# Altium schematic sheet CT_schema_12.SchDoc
size 278 x 170 mm
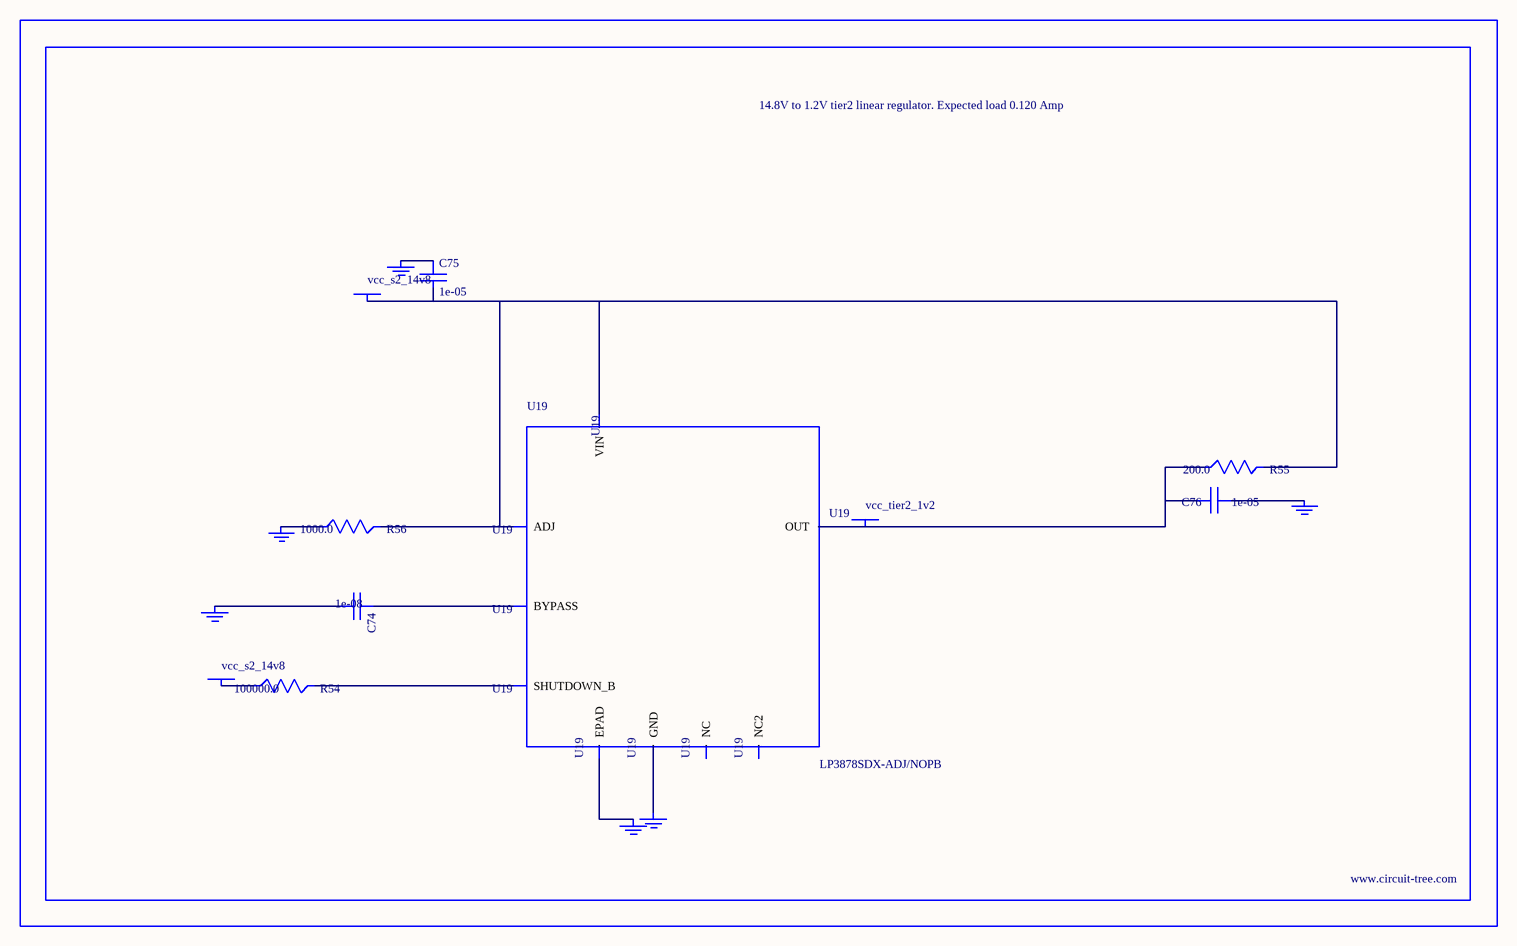
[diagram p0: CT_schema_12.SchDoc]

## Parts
BORDER11  (no value)
C74  1e-08  [C0402]
C75  1e-05  [C1210]
C76  1e-05  [C0805]
GND_INSTANCE_11_0  (no value)
GND_INSTANCE_11_1  (no value)
GND_INSTANCE_11_2  (no value)
GND_INSTANCE_11_3  (no value)
GND_INSTANCE_11_4  (no value)
GND_INSTANCE_11_5  (no value)
POWER_INSTANCE_11_0  vcc_s2_14v8
POWER_INSTANCE_11_1  vcc_s2_14v8
POWER_INSTANCE_11_2  vcc_tier2_1v2
R54  100000.0  [R0603]
R55  200.0  [R0603]
R56  1000.0  [R0603]
U19  LP3878SDX-ADJ/NOPB  [WSON-8]

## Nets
NetC74_1: C74.1 U19.1(BYPASS)
NetC74_2: C74.2 GND_INSTANCE_11_0.0(GND)
NetC75_1: C75.1 GND_INSTANCE_11_1.0(GND)
NetC75_2: C75.2 POWER_INSTANCE_11_0.0(PWR) R55.2 R56.2 U19.4(VIN) U19.6(ADJ)
NetC76_1: C76.1 GND_INSTANCE_11_2.0(GND)
NetC76_2: C76.2 POWER_INSTANCE_11_2.0(PWR) R55.1 U19.5(OUT)
NetGND_INSTANCE_11_3_0: GND_INSTANCE_11_3.0(GND) R56.1
NetGND_INSTANCE_11_4_0: GND_INSTANCE_11_4.0(GND) U19.PAD(EPAD)
NetGND_INSTANCE_11_5_0: GND_INSTANCE_11_5.0(GND) U19.3(GND)
NetPOWER_INSTANCE_11_1_0: POWER_INSTANCE_11_1.0(PWR) R54.1
NetR54_2: R54.2 U19.8(SHUTDOWN_B)

Not connected (* = marked no-connect by the designer): U19 2(NC) 7(NC2)

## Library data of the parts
BORDER11 = BORDER_PAGE11
C74 = C0402C103K3RAC
C75 = C1210C106K5PACTU
C76 = GRM219R60J106ME19D
GND_INSTANCE_11_0-GND_INSTANCE_11_5 = GND
POWER_INSTANCE_11_0-POWER_INSTANCE_11_2 = PWR
R54 = RC0603JR-07100KL
R55 = RC0603JR-07200RL
R56 = RC0603JR-071KL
